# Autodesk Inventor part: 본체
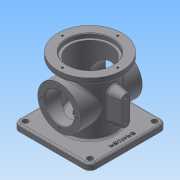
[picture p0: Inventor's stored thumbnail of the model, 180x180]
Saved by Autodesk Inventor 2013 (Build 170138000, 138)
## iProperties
Created: 2017-08
Part Number: 본체
Material: 알루미늄 6061
Document SubType Name: Modeling
Designer: mduedu
Density: 2.71 g/cm^3
Mass: 951.043 g
Surface Area: 966.537 cm^2
Volume: 350.938 cm^3
Author: mduedu
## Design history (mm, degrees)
sketch "스케치1"
  geometry: L1 (-62.5, -62.5)-(62.5, -62.5); L2 (62.5, -62.5)-(62.5, 62.5); L3 (62.5, 62.5)-(-62.5, 62.5); L4 (-62.5, 62.5)-(-62.5, -62.5); L5 (-62.5, -62.5)-(62.5, 62.5); L6 (62.5, -62.5)-(-62.5, 62.5); 1 further point
  constraints: 12 end point, 2 midpoint, 2 parallel, 1 horizontal, 1 perpendicular
  dimensions: "d232" = 125 distance of L3.end L2.end; "d233" = 125 distance of L2.end L1.end
extrude "돌출1" new body sketch "스케치1" distance "d5" = 10; taper "d6" = 0 deg
sketch "스케치2"
  geometry: C1 r 38 at (0, 0); 1 further point
  constraints: 1 centre point, 1 coincident
  dimensions: "d111" = 76 diameter of C1
extrude "돌출2" join sketch "스케치2" distance "d12" = 88; taper "d13" = 0 deg
sketch "스케치3"
  geometry: C1 r 52.5 at (0, 0); 1 further point
  constraints: 1 centre point, 1 coincident
  dimensions: "d114" = 105 diameter of C1
extrude "돌출3" join sketch "스케치3" distance "d19" = 10; taper "d20" = 0 deg
sketch "스케치4"
  geometry: C1 r 33 at (0, 0); 1 further point
  constraints: 1 centre point, 1 coincident
  dimensions: "d115" = 66 diameter of C1
extrude "돌출4" cut sketch "스케치4" distance "d26" = 86; taper "d27" = 0 deg
sketch "스케치5"
  geometry: C1 r 37 at (0, 0); 1 further point
  constraints: 1 centre point, 1 coincident
  dimensions: "d116" = 74 diameter of C1
extrude "돌출5" cut sketch "스케치5" distance "d29" = 7; taper "d30" = 0 deg
node "작업 평면1"
sketch "스케치18"
  geometry: L1 (-62.5, 0)-(62.5, 0) reference; C1 r 35 at (0, 54); 1 further point
  constraints: 1 centre point, 1 vertical alignment
  dimensions: "d118" = 70 diameter of C1; "d234" = 54 distance from line of C1.centre L1
extrude "돌출9" join sketch "스케치18" stored distance "d120" = 10; taper "d121" = 0 deg
hole "구멍8" diameter "d124" = 48; stored, may be unused: countersink angle "d128" = 90 deg, drill point angle "d130" = 118 deg; dims "d122" = 10, "d123" = 10, "d125" = 6, "d126" = 4, "d127" = 2, "d129" = 8
sketch "스케치9"
  geometry: C1 r 33 at (0, 0); 1 further point
  constraints: 1 centre point, 1 coincident
  dimensions: "d131" = 66 diameter of C1
extrude "돌출8" cut sketch "스케치9" distance "d43" = 16; taper "d44" = 0 deg
node "작업 평면2"
fillet "모깎기9" dims "d137" = 3
fillet "모깎기10" dims "d138" = 3
chamfer "모따기2" distance "d139" = 1; stored, may be unused: second distance "d140" = 2, angle "d141" = 45 deg
fillet "모깎기11" dims "d142" = 3
fillet "모깎기12" dims "d143" = 3
fillet "모깎기13" dims "d144" = 3
node "작업 평면3"
sketch "스케치20"
  geometry: L1 (108, -52.5)-(108, 52.5) reference; L2 (37, 7)-(71, 7); L3 (37, -7)-(71, -7); L4 (0, -33)-(0, 33) reference; A1 r 7 centre (37, 0) between (37, 7) and (37, -7); A2 r 7 centre (71, 0) between (71, 7) and (71, -7); 1 further point
  constraints: 4 end point, 4 point on circle, 3 tangent, 2 centre point, 2 horizontal alignment, 1 parallel, 1 perpendicular
  dimensions: "d203" = 14 diameter of A1; "d206" = 30 distance edge to line of A2 L1; "d207" = 48 dimension on A2 A1 (derived); "d236" = 30 distance edge to line of A1 L4
extrude "돌출10" join sketch "스케치20" stored distance "d152" = 10; taper "d153" = 10 deg
sketch "스케치21"
  geometry: C1 r 7 at (0, 71) reference; C2 r 7 at (0, 37) reference; 3 further points
  constraints: 2 coincident
hole "구멍12" sketch "스케치21" at (0, 71), (0, 37) diameter "d219" = 4.134; stored, may be unused: countersink angle "d223" = 90 deg, drill point angle "d225" = 118 deg; dims "d220" = 6, "d221" = 4, "d222" = 2, "d224" = 8
fillet "모깎기18" dims "d229" = 3
sketch "스케치23"
  geometry: C1 r 20 at (0, 0); 1 further point
  constraints: 1 centre point, 1 coincident
  dimensions: "d168" = 40 diameter of C1
extrude "돌출12" cut sketch "스케치23" stored distance "d169" = 148.25; taper "d170" = 0 deg
sketch "스케치28"
  geometry: L1 (62.5, -62.5)-(62.5, 62.5) reference; 2 further points
  constraints: 1 horizontal alignment, 1 other
  dimensions: "d238" = 10 distance from line of point (52.5, 0) L1
feature "엠보싱4" sketch "스케치28" dims "d239" = 0.5, "d240" = 0
sketch "스케치25" dims "d178" = 58
  geometry: C1 r 35 at (0, 0) reference; 3 further points
  constraints: 2 vertical alignment, 1 coincident, 2 other
hole "구멍10" sketch "스케치25" at (0, 29) diameter "d179" = 3.242; stored, may be unused: countersink angle "d183" = 90 deg, drill point angle "d185" = 118 deg; dims "d180" = 4, "d181" = 4, "d182" = 2, "d184" = 6
sketch "스케치26" dims "d189" = 90
  geometry: 3 further points
  constraints: 2 vertical alignment, 1 coincident, 2 other
hole "구멍11" sketch "스케치26" at (0, 45) diameter "d190" = 3.242; stored, may be unused: countersink angle "d194" = 90 deg, drill point angle "d196" = 118 deg; dims "d191" = 4, "d192" = 4, "d193" = 2, "d195" = 6
chamfer "모따기4" distance "d200" = 1; stored, may be unused: second distance "d201" = 2, angle "d202" = 45 deg
fillet "모깎기19" dims "d241" = 10
sketch "스케치29"
  geometry: A1 r 10 centre (-52.5, 52.5) between (-52.5, 62.5) and (-62.5, 52.5) reference; A2 r 10 centre (52.5, 52.5) between (62.5, 52.5) and (52.5, 62.5) reference; A3 r 10 centre (52.5, -52.5) between (52.5, -62.5) and (62.5, -52.5) reference; A4 r 10 centre (-52.5, -52.5) between (-62.5, -52.5) and (-52.5, -62.5) reference; 5 further points
  constraints: 4 coincident
hole "구멍13" sketch "스케치29" at (-52.5, 52.5), (52.5, 52.5), (52.5, -52.5), (-52.5, -52.5) diameter "d242" = 9; stored, may be unused: countersink angle "d246" = 90 deg, drill point angle "d248" = 118 deg; dims "d243" = 6, "d244" = 4, "d245" = 2, "d247" = 8
fillet "모깎기20" dims "d249" = 3
node "솔리드1"
mirror "대칭2"
pattern_circular "원형 패턴1" dims angle "d187" = 360 deg
mirror "대칭3"
pattern_circular "원형 패턴2" dims angle "d198" = 360 deg
other parameters: "d147" = 58
